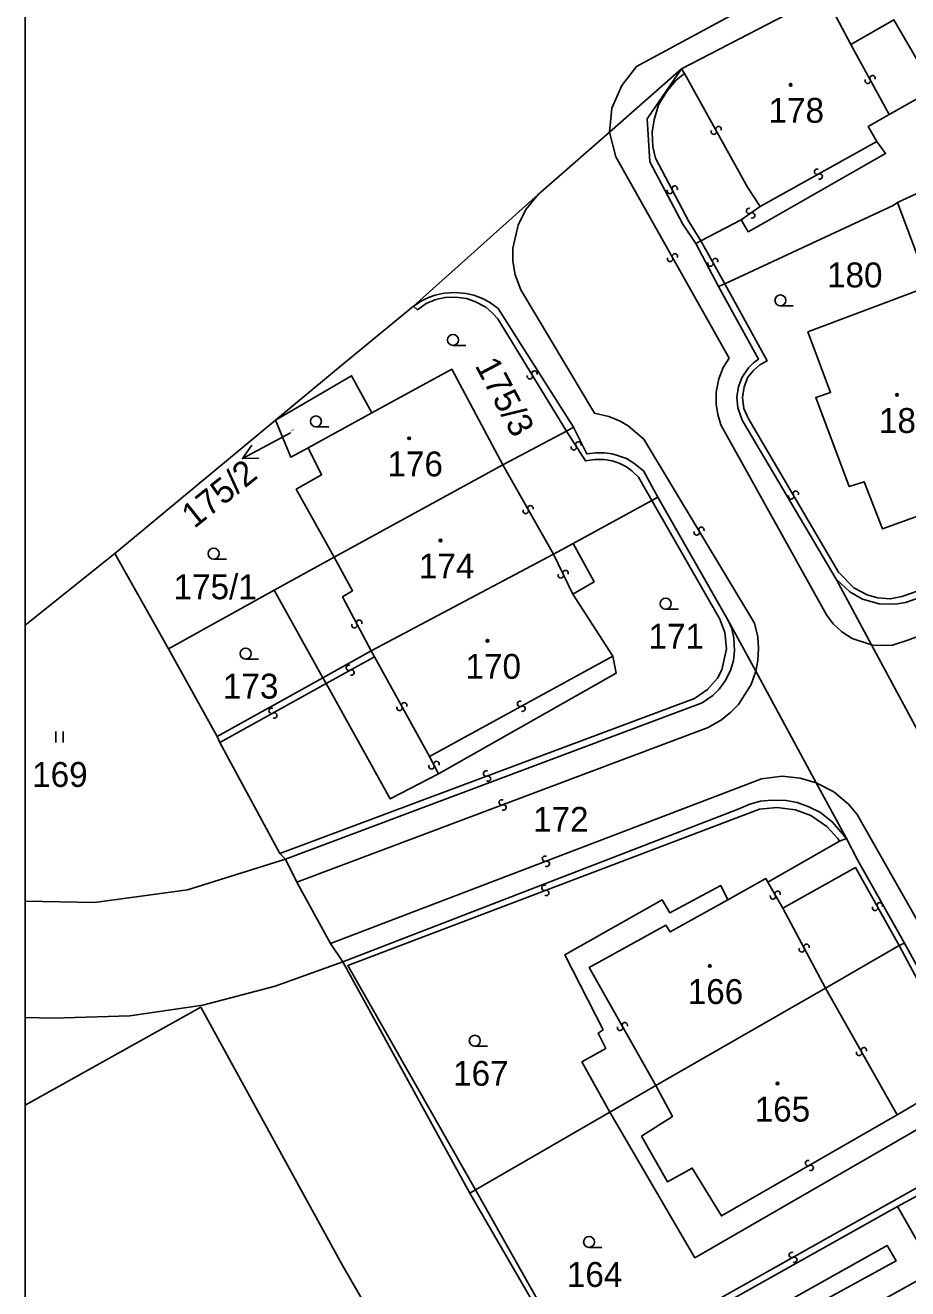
# Model space of a CAD drawing. Extents: x -600391 to -599491, y -1160176 to -1159402.
# Drawn here: x -600391 to -600330.7, y -1159747.5 to -1159661.1 of the extents above; entities that cross this region are included whole.
import ezdxf

# ---------------------------------------------------------------- set-up
doc = ezdxf.new("R2010")
doc.units = 0
for name, color, linetype in [('Level 1', 7, 'Continuous'), ('Level 13', 7, 'Continuous'), ('Level 3', 7, 'Continuous'), ('Level 4', 7, 'Continuous'), ('Level 5', 7, 'Continuous'), ('Level 57', 7, 'Continuous'), ('Vrstva 63', 7, 'Continuous')]:
    doc.layers.add(name, color=color, linetype=linetype)

msp = doc.modelspace()

# ---------------------------------------------------------------- linework, layer by layer
at = {"layer": 'Level 1'}
msp.add_line((-600391.008, -1159702.116), (-600384.88, -1159697.23), dxfattribs=at)
for points in [[(-600107.73, -1159499.45), (-600113.87, -1159502.94), (-600201.37, -1159552.29), (-600219.23, -1159562.65), (-600266.03, -1159590.55), (-600270.37, -1159592.37), (-600271.85, -1159593.21), (-600272.01, -1159592.83), (-600281.12, -1159598.11), (-600280.42, -1159599.25), (-600280.87, -1159599.52), (-600276.57, -1159606.52), (-600297.82, -1159620.52), (-600312.66, -1159632.26), (-600336.82, -1159651.44), (-600337.7, -1159652.95), (-600337.93, -1159654.45), (-600337.54, -1159656.13), (-600336.82, -1159657.21), (-600349.22, -1159663.94), (-600350.24, -1159665.24), (-600350.91, -1159666.77), (-600351.08, -1159668.42)], [(-600351.08, -1159668.42), (-600346.15, -1159664.1), (-600336.38, -1159659.02)], [(-600346.15, -1159664.1), (-600336.38, -1159659.02)], [(-600334.57, -1159662.42), (-600336.38, -1159659.02)], [(-600331.95, -1159667.22), (-600328.87, -1159665.49), (-600331.63, -1159660.75), (-600334.57, -1159662.42)], [(-600351.08, -1159668.42), (-600346.15, -1159664.1)], [(-600345.17, -1159676.04), (-600346.05, -1159674.72), (-600348.31, -1159670.45), (-600348.5, -1159667.52), (-600346.15, -1159664.1)], [(-600332.8, -1159669.06), (-600333.39, -1159668.04), (-600331.95, -1159667.22)], [(-600391.008, -1159702.116), (-600384.88, -1159697.23), (-600373.9, -1159688.12), (-600369.2, -1159684.22), (-600364.48, -1159680.31), (-600355.94, -1159672.69), (-600351.08, -1159668.42)], [(-600355.94, -1159672.69), (-600351.08, -1159668.42)], [(-600342.08, -1159674.41), (-600341.6, -1159675.23), (-600340.34, -1159674.53), (-600332.21, -1159669.89), (-600332.8, -1159669.06)], [(-600331.38, -1159673.24), (-600323.27, -1159669.48)], [(-600364.48, -1159680.31), (-600355.94, -1159672.69)], [(-600343.19, -1159678.79), (-600331.69, -1159673.44), (-600331.38, -1159673.24)], [(-600329.25, -1159678.95), (-600331.38, -1159673.24)], [(-600344.83, -1159675.84), (-600342.08, -1159674.41)], [(-600345.17, -1159676.04), (-600344.83, -1159675.84)], [(-600343.63, -1159678.98), (-600345.17, -1159676.04)], [(-600353.53, -1159688.59), (-600358.68, -1159680.48), (-600359.27, -1159680.05), (-600359.76, -1159679.8), (-600360.35, -1159679.57), (-600360.88, -1159679.45), (-600361.62, -1159679.38), (-600362.38, -1159679.43), (-600362.98, -1159679.56), (-600363.45, -1159679.73), (-600363.94, -1159679.97), (-600364.48, -1159680.31)], [(-600343.63, -1159678.98), (-600343.19, -1159678.79)], [(-600335.58, -1159698.99), (-600342.01, -1159688.11), (-600342.3, -1159687.27), (-600342.36, -1159686.53), (-600342.25, -1159685.81), (-600342, -1159685.16), (-600341.58, -1159684.54), (-600341.24, -1159684.2), (-600340.89, -1159683.94), (-600343.63, -1159678.98)], [(-600326.73, -1159693.48), (-600332.42, -1159695.54), (-600333.67, -1159692.32), (-600334.69, -1159692.64), (-600336.97, -1159686.56), (-600335.96, -1159686.22), (-600337.51, -1159682.08), (-600329.64, -1159679.1), (-600329.25, -1159678.95)], [(-600364.48, -1159680.31), (-600369.2, -1159684.22), (-600373.9, -1159688.12)], [(-600358.36, -1159691.16), (-600361.85, -1159684.63), (-600367.31, -1159687.61)], [(-600367.31, -1159687.61), (-600368.7, -1159685.07), (-600373.9, -1159688.12)], [(-600384.88, -1159697.23), (-600373.9, -1159688.12)], [(-600371.66, -1159689.99), (-600372.85, -1159690.64), (-600373.9, -1159688.12)], [(-600371.66, -1159689.99), (-600367.31, -1159687.61)], [(-600354.01, -1159688.85), (-600358.36, -1159691.16)], [(-600353.53, -1159688.59), (-600354.01, -1159688.85)], [(-600347.77, -1159693.37), (-600348.76, -1159691.58), (-600349.41, -1159691.04), (-600349.92, -1159690.74), (-600350.45, -1159690.54), (-600350.9, -1159690.42), (-600351.41, -1159690.34), (-600352, -1159690.34), (-600352.63, -1159690.42), (-600353.53, -1159688.59)], [(-600369.9, -1159697.48), (-600372.49, -1159692.83), (-600370.75, -1159691.85), (-600371.66, -1159689.99)], [(-600358.36, -1159691.16), (-600369.9, -1159697.48)], [(-600347.77, -1159693.37), (-600348.19, -1159693.59)], [(-600347.77, -1159693.37), (-600343.07, -1159701.6), (-600342.99, -1159701.75)], [(-600348.19, -1159693.59), (-600353.55, -1159696.54)], [(-600353.55, -1159696.54), (-600354.91, -1159697.28)], [(-600353.57, -1159700), (-600352.13, -1159699.16), (-600353.55, -1159696.54)], [(-600381.22, -1159703.75), (-600384.88, -1159697.23)], [(-600369.9, -1159697.48), (-600374, -1159699.74)], [(-600354.91, -1159697.28), (-600367.36, -1159703.88)], [(-600324.51, -1159698.2), (-600330.17, -1159700.35), (-600330.84, -1159700.58), (-600331.53, -1159700.69), (-600332.65, -1159700.66), (-600333.77, -1159700.35), (-600334.65, -1159699.85), (-600335.58, -1159698.99)], [(-600333.16, -1159703.47), (-600335.58, -1159698.99)], [(-600374, -1159699.74), (-600381.22, -1159703.75)], [(-600370.67, -1159705.73), (-600374, -1159699.74)], [(-600353.57, -1159700), (-600350.84, -1159704.24)], [(-600373.23, -1159718.12), (-600344.74, -1159707.43), (-600344.02, -1159706.94), (-600343.57, -1159706.5), (-600343.16, -1159705.94), (-600342.81, -1159705.23), (-600342.59, -1159704.54), (-600342.53, -1159703.87), (-600342.57, -1159703.01), (-600342.71, -1159702.36), (-600342.99, -1159701.75)], [(-600341.08, -1159705.27), (-600342.99, -1159701.75)], [(-600377.89, -1159709.74), (-600381.22, -1159703.75)], [(-600329.03, -1159711.13), (-600333.16, -1159703.47)], [(-600367.36, -1159703.88), (-600370.67, -1159705.73)], [(-600362.77, -1159712.28), (-600350.62, -1159705.41), (-600350.84, -1159704.24)], [(-600336.94, -1159712.9), (-600341.08, -1159705.27)], [(-600370.67, -1159705.73), (-600377.89, -1159709.74)], [(-600370.67, -1159705.73), (-600370.45, -1159706.12)], [(-600370.45, -1159706.12), (-600366.06, -1159714), (-600362.77, -1159712.28)], [(-600377.72, -1159710.15), (-600377.89, -1159709.74)], [(-600373.61, -1159717.73), (-600377.72, -1159710.15)], [(-600334.88, -1159716.71), (-600336.94, -1159712.9)], [(-600369.29, -1159725.14), (-600342.27, -1159714.71), (-600341.48, -1159714.37), (-600340.74, -1159714.15), (-600339.99, -1159714.08), (-600339, -1159714.11), (-600338.24, -1159714.25), (-600337.44, -1159714.54), (-600336.64, -1159714.94), (-600335.83, -1159715.58), (-600334.88, -1159716.71)], [(-600334.88, -1159716.71), (-600335.34, -1159716.9)], [(-600334.88, -1159716.71), (-600334.11, -1159718.17), (-600330.91, -1159723.87)], [(-600335.34, -1159716.9), (-600340.26, -1159719.69)], [(-600373.23, -1159718.12), (-600373.61, -1159717.73)], [(-600373.23, -1159718.12), (-600372.44, -1159719.7)], [(-600372.44, -1159719.7), (-600370.15, -1159723.88)], [(-600342.99, -1159720.9), (-600343.46, -1159719.93), (-600346.95, -1159721.78), (-600347.48, -1159720.91), (-600354.13, -1159724.67), (-600351.51, -1159729.79), (-600351.85, -1159730.02), (-600351.33, -1159731.06), (-600352.96, -1159731.98), (-600351.06, -1159735.42)], [(-600340.26, -1159719.69), (-600340.39, -1159719.45), (-600342.99, -1159720.9)], [(-600370.15, -1159723.88), (-600369.29, -1159725.14)], [(-600331.27, -1159724.02), (-600336.3, -1159726.93)], [(-600330.91, -1159723.87), (-600331.27, -1159724.02)], [(-600330.91, -1159723.87), (-600326.12, -1159732.59), (-600325.37, -1159733.88)], [(-600369.29, -1159725.14), (-600373.92, -1159726.81), (-600378.86, -1159728.09), (-600383.86, -1159728.84), (-600389.07, -1159729), (-600391.008, -1159728.934)], [(-600369.29, -1159725.14), (-600360.63, -1159740.95)], [(-600336.3, -1159726.93), (-600347.9, -1159733.59)], [(-600391.008, -1159734.943), (-600379, -1159728.24), (-600369.34, -1159745.86), (-600364.71, -1159753.86)], [(-600347.9, -1159733.59), (-600351.06, -1159735.42)], [(-600325.77, -1159734.15), (-600345.23, -1159745.37), (-600351.06, -1159735.42)], [(-600351.06, -1159735.42), (-600360.24, -1159740.73)], [(-600323.27, -1159737.47), (-600331.38, -1159741.87)], [(-600360.24, -1159740.73), (-600360.63, -1159740.95)], [(-600360.63, -1159740.95), (-600353.06, -1159754.02)], [(-600331.38, -1159741.87), (-600353.06, -1159754.02)], [(-600328.85, -1159746.29), (-600350.68, -1159758.38)]]:
    msp.add_lwpolyline(points, dxfattribs=at)
at = {"layer": 'Level 13'}
for centre, start, end in [((-600333.422, -1159664.907), 155.78546, 28.37546), ((-600333.097, -1159664.733), 335.99992, 208.09791), ((-600343.942, -1159668.388), 156.38976, 28.48776), ((-600343.619, -1159668.211), 336.1753, 208.7653), ((-600336.879, -1159671.129), 66.30424, 298.89424), ((-600336.702, -1159671.452), 246.5187, 118.6167), ((-600346.944, -1159672.444), 155.093, 27.19099), ((-600346.617, -1159672.275), 334.87854, 207.46854), ((-600341.534, -1159673.807), 72.06789, 304.16588), ((-600341.326, -1159674.112), 251.85343, 124.44343), ((-600346.608, -1159676.911), 336.7127, 208.8107), ((-600346.931, -1159677.089), 156.49825, 29.08825), ((-600344.172, -1159677.408), 156.44383, 28.54182), ((-600343.849, -1159677.231), 336.22937, 208.81937), ((-600356.202, -1159684.925), 338.87174, 210.96974), ((-600356.517, -1159685.115), 158.65729, 31.24729), ((-600353.516, -1159689.968), 159.46561, 32.05561), ((-600353.203, -1159689.773), 339.68007, 211.77806), ((-600338.66, -1159693.322), 157.74069, 29.83868), ((-600338.341, -1159693.138), 337.52623, 210.11623), ((-600356.801, -1159694.31), 156.56934, 29.15934), ((-600356.478, -1159694.131), 336.7838, 208.88179), ((-600345.108, -1159695.784), 158.19565, 30.78565), ((-600344.791, -1159695.596), 338.41011, 210.50811), ((-600354.074, -1159698.56), 333.59976, 205.69776), ((-600354.405, -1159698.721), 153.38531, 25.97531), ((-600368.504, -1159702.125), 155.34842, 27.44642), ((-600368.177, -1159701.954), 335.13397, 207.72397), ((-600368.889, -1159705.039), 66.22758, 298.81758), ((-600368.712, -1159705.362), 246.44203, 118.54003), ((-600374.168, -1159707.978), 66.37378, 298.47178), ((-600365.422, -1159707.778), 156.30593, 28.40393), ((-600365.099, -1159707.602), 336.09148, 208.68148), ((-600357.187, -1159707.507), 66.07282, 298.17082), ((-600357.012, -1159707.832), 245.85837, 118.44837), ((-600373.991, -1159708.301), 246.15932, 118.74932), ((-600362.906, -1159711.607), 334.11046, 206.70046), ((-600363.235, -1159711.772), 154.32491, 26.42291), ((-600359.504, -1159712.267), 57.64783, 290.23783), ((-600359.377, -1159712.613), 237.86228, 109.96028), ((-600358.443, -1159714.237), 57.99128, 290.08927), ((-600358.316, -1159714.583), 237.77682, 110.36682), ((-600355.484, -1159718.087), 58.27328, 290.37128), ((-600355.355, -1159718.432), 238.05882, 110.64882), ((-600355.524, -1159720.087), 58.16802, 290.26602), ((-600355.395, -1159720.432), 237.95357, 110.54357), ((-600339.9, -1159720.672), 157.31511, 29.90511), ((-600339.58, -1159720.489), 337.52956, 209.62756), ((-600332.922, -1159721.449), 156.66409, 28.76209), ((-600332.599, -1159721.271), 336.44964, 209.03964), ((-600337.923, -1159724.286), 155.33979, 27.92979), ((-600337.597, -1159724.114), 335.55424, 207.65224), ((-600350.351, -1159729.649), 156.92586, 29.02386), ((-600350.029, -1159729.47), 336.71141, 209.30141), ((-600334.011, -1159731.36), 156.63199, 29.22199), ((-600333.689, -1159731.181), 336.84644, 208.94444), ((-600337.501, -1159738.9), 67.05181, 299.64181), ((-600337.32, -1159739.221), 247.26626, 119.36426), ((-600338.619, -1159745.179), 66.46723, 299.05723), ((-600338.441, -1159745.502), 246.68169, 118.77968)]:
    msp.add_arc(centre, 0.184, start, end, dxfattribs=at)
at = {"layer": 'Level 3'}
for points in [[(-600334.57, -1159662.42), (-600331.95, -1159667.22)], [(-600344.83, -1159675.84), (-600345.65, -1159674.52), (-600347.92, -1159670.2), (-600348.12, -1159669.42), (-600348.15, -1159668.43), (-600348.03, -1159667.58), (-600347.72, -1159666.56), (-600347.14, -1159665.59), (-600346.52, -1159664.87), (-600345.94, -1159664.42)], [(-600345.94, -1159664.42), (-600346.15, -1159664.1)], [(-600340.78, -1159673.51), (-600341.63, -1159672.19), (-600345.94, -1159664.42)], [(-600240.59, -1159667), (-600241.21, -1159668.2), (-600242.18, -1159669.27), (-600243.09, -1159670.01), (-600244.19, -1159670.6), (-600330.67, -1159703.15), (-600331.73, -1159703.48), (-600332.86, -1159703.51), (-600333.16, -1159703.47)], [(-600351.08, -1159668.42), (-600350.64, -1159670.11), (-600342.9, -1159683.88), (-600343.3, -1159684.52), (-600343.61, -1159685.28), (-600343.78, -1159686.19), (-600343.78, -1159687.01), (-600343.67, -1159687.73), (-600343.46, -1159688.42), (-600336.25, -1159701.42), (-600335.79, -1159702.04), (-600335.2, -1159702.59), (-600334.48, -1159703.04), (-600333.16, -1159703.47)], [(-600332.8, -1159669.06), (-600340.78, -1159673.51)], [(-600355.94, -1159672.69), (-600356.79, -1159673.7), (-600357.32, -1159674.77), (-600357.67, -1159676.34), (-600357.67, -1159677.24), (-600357.51, -1159678.18), (-600357.14, -1159679.19), (-600352.1, -1159687.63), (-600351.11, -1159687.85), (-600350.34, -1159688.17), (-600349.79, -1159688.49), (-600348.73, -1159689.4), (-600341.16, -1159701.98), (-600340.94, -1159702.92), (-600340.89, -1159703.7), (-600340.93, -1159704.53), (-600341.08, -1159705.27)], [(-600342.08, -1159674.41), (-600340.78, -1159673.51)], [(-600343.19, -1159678.79), (-600344.83, -1159675.84)], [(-600324.73, -1159697.83), (-600330.36, -1159699.91), (-600331.09, -1159700.17), (-600331.88, -1159700.33), (-600332.75, -1159700.25), (-600333.47, -1159700.05), (-600334.38, -1159699.58), (-600335.42, -1159698.5), (-600341.59, -1159687.97), (-600341.89, -1159687.31), (-600341.99, -1159686.56), (-600341.87, -1159685.84), (-600341.62, -1159685.18), (-600341.24, -1159684.71), (-600340.79, -1159684.32), (-600340.3, -1159684.06), (-600343.19, -1159678.79)], [(-600364.48, -1159680.31), (-600364.2, -1159680.56), (-600363.6, -1159680.14), (-600362.94, -1159679.87), (-600362.31, -1159679.73), (-600361.58, -1159679.69), (-600360.85, -1159679.8), (-600360.27, -1159679.99), (-600359.53, -1159680.39), (-600359.06, -1159680.79), (-600358.71, -1159681.18), (-600354.01, -1159688.85)], [(-600354.01, -1159688.85), (-600352.72, -1159690.89), (-600352.07, -1159690.79), (-600351.44, -1159690.79), (-600350.88, -1159690.89), (-600350.42, -1159691.05), (-600349.92, -1159691.31), (-600349.55, -1159691.57), (-600349.09, -1159692.01), (-600348.19, -1159693.59)], [(-600358.36, -1159691.16), (-600354.91, -1159697.28)], [(-600348.19, -1159693.59), (-600343.53, -1159701.71), (-600343.19, -1159702.62), (-600343.07, -1159703.75), (-600343.4, -1159705.18), (-600343.7, -1159705.74), (-600344.37, -1159706.53), (-600345.27, -1159707.14), (-600373.61, -1159717.73)], [(-600367.36, -1159703.88), (-600369.32, -1159700.19), (-600368.63, -1159699.77), (-600369.9, -1159697.48)], [(-600354.91, -1159697.28), (-600353.57, -1159700)], [(-600367.14, -1159704.28), (-600370.45, -1159706.12)], [(-600367.14, -1159704.28), (-600367.36, -1159703.88)], [(-600363.37, -1159711.1), (-600367.14, -1159704.28)], [(-600363.37, -1159711.1), (-600350.84, -1159704.24)], [(-600372.44, -1159719.7), (-600344.32, -1159709.12), (-600343.41, -1159708.6), (-600342.79, -1159708.08), (-600342.25, -1159707.54), (-600341.4, -1159706.17), (-600341.08, -1159705.27)], [(-600377.72, -1159710.15), (-600370.45, -1159706.12)], [(-600362.77, -1159712.28), (-600363.37, -1159711.1)], [(-600370.15, -1159723.88), (-600340.69, -1159712.63), (-600339.28, -1159712.45), (-600338.04, -1159712.58), (-600336.94, -1159712.9)], [(-600336.94, -1159712.9), (-600335.74, -1159713.51), (-600334.73, -1159714.36), (-600334.14, -1159715.06), (-600271.35, -1159825.67), (-600271.05, -1159826.26), (-600270.91, -1159826.95), (-600270.93, -1159827.71), (-600271.14, -1159828.5), (-600271.56, -1159829.2), (-600271.82, -1159829.5)], [(-600360.24, -1159740.73), (-600368.96, -1159725.38), (-600341.97, -1159715.13), (-600340.81, -1159714.71), (-600339.64, -1159714.58), (-600338.35, -1159714.75), (-600337.32, -1159715.14), (-600336.21, -1159715.89), (-600335.49, -1159716.68), (-600335.34, -1159716.9)], [(-600373.23, -1159718.12), (-600379.93, -1159720.21), (-600386.27, -1159721.08), (-600391.008, -1159720.991)], [(-600331.27, -1159724.02), (-600334.26, -1159718.69), (-600339.22, -1159721.48)], [(-600340.26, -1159719.69), (-600339.22, -1159721.48)], [(-600347.9, -1159733.59), (-600352.47, -1159725.53), (-600347.22, -1159722.64), (-600346.93, -1159723.09), (-600342.99, -1159720.9)], [(-600339.22, -1159721.48), (-600336.3, -1159726.93)], [(-600331.27, -1159724.02), (-600326.61, -1159732.77), (-600331.4, -1159735.6)], [(-600336.3, -1159726.93), (-600331.4, -1159735.6)], [(-600331.4, -1159735.6), (-600343.42, -1159742.51), (-600345.42, -1159739.24), (-600347.1, -1159740.18), (-600348.88, -1159737.05), (-600346.77, -1159735.72), (-600347.9, -1159733.59)], [(-600325.77, -1159734.15), (-600324.03, -1159737.2), (-600353.03, -1159753.48), (-600360.24, -1159740.73)], [(-600331.38, -1159741.87), (-600328.85, -1159746.29)], [(-600351.74, -1159756.67), (-600352.17, -1159755.78), (-600332.1, -1159744.52), (-600331.48, -1159745.58), (-600351.74, -1159756.67)]]:
    msp.add_lwpolyline(points, dxfattribs=at)
at = {"layer": 'Level 5'}
for p, q in [((-600339.39, -1159680.3), (-600338.515, -1159680.3)), ((-600361.77, -1159683), (-600360.895, -1159683)), ((-600371.14, -1159688.57), (-600370.265, -1159688.57)), ((-600378.13, -1159697.61), (-600377.255, -1159697.61)), ((-600347.23, -1159701.03), (-600346.355, -1159701.03)), ((-600375.94, -1159704.44), (-600375.065, -1159704.44)), ((-600388.91, -1159710.135), (-600388.91, -1159709.384)), ((-600388.41, -1159710.135), (-600388.41, -1159709.384)), ((-600360.28, -1159730.91), (-600359.405, -1159730.91)), ((-600352.47, -1159744.66), (-600351.595, -1159744.66))]:
    msp.add_line(p, q, dxfattribs=at)
for centre, radius in [((-600338.69, -1159665.18), 0.09), ((-600338.69, -1159665.18), 0.0521), ((-600339.39, -1159679.925), 0.375), ((-600361.77, -1159682.625), 0.375), ((-600331.42, -1159686.38), 0.09), ((-600331.42, -1159686.38), 0.0521), ((-600371.14, -1159688.195), 0.375), ((-600364.77, -1159689.35), 0.09), ((-600364.77, -1159689.35), 0.0521), ((-600378.13, -1159697.235), 0.375), ((-600362.62, -1159696.33), 0.09), ((-600362.62, -1159696.33), 0.0521), ((-600347.23, -1159700.655), 0.375), ((-600375.94, -1159704.065), 0.375), ((-600359.41, -1159703.19), 0.09), ((-600359.41, -1159703.19), 0.0521), ((-600344.21, -1159725.42), 0.09), ((-600344.21, -1159725.42), 0.0521), ((-600360.28, -1159730.535), 0.375), ((-600339.59, -1159733.46), 0.09), ((-600339.59, -1159733.46), 0.0521), ((-600352.47, -1159744.285), 0.375)]:
    msp.add_circle(centre, radius, dxfattribs=at)
at = {"layer": 'Level 57'}
for p, q in [((-600372.87, -1159688.97), (-600373.518, -1159689.319)), ((-600373.518, -1159689.319), (-600376.16, -1159690.74))]:
    msp.add_line(p, q, dxfattribs=at)
msp.add_lwpolyline([(-600375.042, -1159690.707), (-600376.16, -1159690.74), (-600375.516, -1159689.826)], dxfattribs=at)
at = {"layer": 'Vrstva 63'}
msp.add_lwpolyline([(-600391.008, -1159401.769), (-599490.773, -1159401.769), (-599490.773, -1160176.079), (-600391.008, -1160176.079)], close=True, dxfattribs=at)

# ---------------------------------------------------------------- texts
at = {"layer": 'Level 4'}
for s, p in [('178', (-600340.199, -1159667.78)), ('180', (-600336.204, -1159679.03)), ('181', (-600332.654, -1159688.98)), ('176', (-600366.252, -1159691.95)), ('174', (-600364.102, -1159698.93)), ('175/1', (-600380.871, -1159700.35)), ('171', (-600348.405, -1159703.73)), ('170', (-600360.915, -1159705.79)), ('173', (-600377.498, -1159707.14)), ('169', (-600390.537, -1159713.18)), ('172', (-600356.297, -1159716.25)), ('166', (-600345.727, -1159728.02)), ('167', (-600361.762, -1159733.61)), ('165', (-600341.149, -1159736.06)), ('164', (-600353.987, -1159747.36))]:
    msp.add_text(s, height=1.7, dxfattribs=at).set_placement(p)
for s, height, rotation, p in [('175/3', 1.7, 297.9, (-600360.302, -1159684.371)), ('175/2', 0.1, 38.7, (-600372.87, -1159688.97))]:
    msp.add_text(s, height=height, rotation=rotation, dxfattribs=at).set_placement(p)
at = {"layer": 'Level 57'}
msp.add_text('175/2', height=1.7, rotation=38.7, dxfattribs=at).set_placement((-600379.457, -1159695.559))

doc.saveas('drawing.dxf')
